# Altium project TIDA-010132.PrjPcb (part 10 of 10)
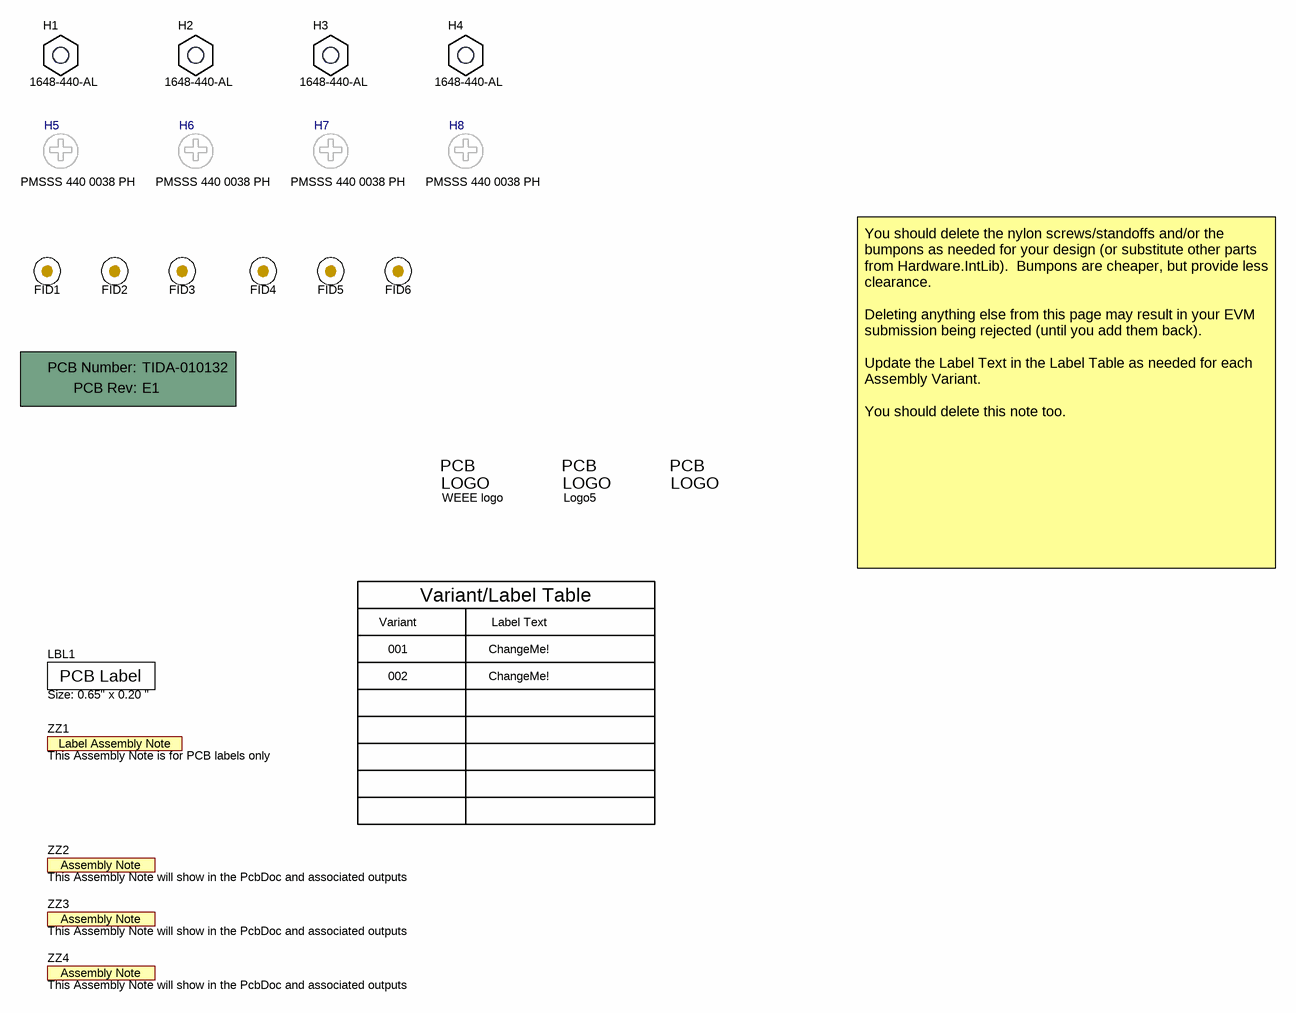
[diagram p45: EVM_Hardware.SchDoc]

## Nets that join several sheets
1P8V_USB: FMC INTERFACE SHEET (9 pins), USB INTERFACE SHEET (34 pins)
3.3V_USB: FMC INTERFACE SHEET (8 pins), CLOCK BUFFER (C419.2 R541.2 U79.16), USB INTERFACE SHEET (40 pins)
+2.5VCLK: CLOCK MAIN SHEET (12 pins), POWER MAIN SHEET1 (6 pins)
+3.3LMK_1: POWER MAIN SHEET1 (5 pins), POWER MAIN SHEET2 (5 pins)
+3.3VCLK: AFE1-LMX2594 (21 pins), CLOCK MAIN SHEET (10 pins), CLOCK MAIN POWER (8 pins), CLOCK BUFFER (14 pins), POWER MAIN SHEET1 (11 pins), POWER MAIN SHEET2 (5 pins), AFE2-LMX2594 (21 pins)
+5V_1: POWER MAIN SHEET1 (J78.1 J78.2 U86.1), POWER MAIN SHEET2 (J55.1 J55.2 U85.1)
+5VIN: FMC INTERFACE SHEET (D7.1 D8.1 D10.1), AFE1-GPIOs (D12.1 D13.1 D14.1), POWER MAIN SHEET1 (6 pins), POWER MAIN SHEET2 (6 pins), USB INTERFACE SHEET (C581.1 R389.1 U33.1), AFE2-GPIOs (D15.1 D16.1 D17.1)
ANALOG_1.0V_1: POWER MAIN SHEET1 (14 pins), POWER MAIN SHEET2 (14 pins)
ANALOG_1.2V_1: POWER MAIN SHEET1 (7 pins), POWER MAIN SHEET2 (7 pins)
ANALOG_1.5V_1: POWER MAIN SHEET1 (7 pins), POWER MAIN SHEET2 (7 pins)
ANALOG_1.8V_1: POWER MAIN SHEET1 (12 pins), POWER MAIN SHEET2 (12 pins)
ANALOG_-1.8V_1: POWER MAIN SHEET1 (7 pins), POWER MAIN SHEET2 (7 pins)
DVDD: AFE1-POWER (41 pins), POWER MAIN SHEET1 (6 pins)
DVDD_1.0V_1: POWER MAIN SHEET1 (13 pins), POWER MAIN SHEET2 (13 pins)
DVDD_2: POWER MAIN SHEET2 (6 pins), AFE2-POWER (41 pins)
GND: 01-MAIN-Sheet (23 pins), FMC INTERFACE SHEET (234 pins), AFE1-RX-INPUTS (96 pins), AFE1-TX-OUTPUTS (45 pins), AFE1-LMX2594 (59 pins), AFE1-POWER (87 pins), AFE1-RX-TX-INTERFACE (26 pins), AFE1-GROUND (136 pins), AFE1-PROGRAMMING INTERFACE (8 pins), AFE1-GPIOs (34 pins), CLOCK MAIN SHEET (72 pins), CLOCK MAIN POWER (26 pins), CLOCK BUFFER (28 pins), POWER MAIN SHEET1 (151 pins), POWER MAIN SHEET2 (140 pins), USB INTERFACE SHEET (94 pins), AFE2-PROGRAMMING INTERFACE (8 pins), AFE2-GPIOs (34 pins), AFE2-RX-INPUTS (96 pins), AFE2-TX-OUTPUTS (45 pins), AFE2-LMX2594 (59 pins), AFE2-POWER (87 pins), AFE2-RX-TX-INTERFACE (26 pins), AFE2-GROUND (136 pins)
RX_1.2V: AFE1-POWER (28 pins), POWER MAIN SHEET1 (5 pins)
RX_1.2V_2: POWER MAIN SHEET2 (5 pins), AFE2-POWER (28 pins)
RX_1.8V: AFE1-POWER (30 pins), POWER MAIN SHEET1 (5 pins)
RX_1.8V_2: POWER MAIN SHEET2 (5 pins), AFE2-POWER (30 pins)
VDDA_1.0V: AFE1-POWER (5 pins), POWER MAIN SHEET1 (5 pins)
VDDA_1.0V_2: POWER MAIN SHEET2 (5 pins), AFE2-POWER (5 pins)
VDDA_1.8V: AFE1-TX-OUTPUTS (16 pins), AFE1-POWER (7 pins), POWER MAIN SHEET1 (5 pins)
VDDA_1.8V_2: POWER MAIN SHEET2 (5 pins), AFE2-TX-OUTPUTS (16 pins), AFE2-POWER (7 pins)
VDDA_SERDES_1.0V: AFE1-POWER (7 pins), POWER MAIN SHEET1 (5 pins)
VDDA_SERDES_1.0V_2: POWER MAIN SHEET2 (5 pins), AFE2-POWER (7 pins)
VDDCLK_1.0V: AFE1-POWER (9 pins), POWER MAIN SHEET1 (5 pins)
VDDCLK_1.0V_2: POWER MAIN SHEET2 (5 pins), AFE2-POWER (9 pins)
VDDE: AFE1-POWER (15 pins), POWER MAIN SHEET1 (5 pins)
VDDE_2: POWER MAIN SHEET2 (5 pins), AFE2-POWER (15 pins)
VDDGPIO_1.8V: AFE1-POWER (C97.1 U3.D17), AFE1-GPIOs (20 pins), POWER MAIN SHEET1 (5 pins)
VDDGPIO_1.8V_2: POWER MAIN SHEET2 (5 pins), AFE2-GPIOs (20 pins), AFE2-POWER (C323.1 U6.D17)
VDDL1_1.0V: AFE1-POWER (9 pins), POWER MAIN SHEET1 (5 pins)
VDDL1_1.0V_2: POWER MAIN SHEET2 (5 pins), AFE2-POWER (9 pins)
VDDL2_1.0V: AFE1-POWER (9 pins), POWER MAIN SHEET1 (5 pins)
VDDL2_1.0V_2: POWER MAIN SHEET2 (5 pins), AFE2-POWER (9 pins)
VDDPLL_1.0V: AFE1-POWER (C73.1 C74.1 U3.K18), POWER MAIN SHEET1 (5 pins)
VDDPLL_1.0V_2: POWER MAIN SHEET2 (5 pins), AFE2-POWER (C299.1 C300.1 U6.K18)
VDDPLL_1.8V: AFE1-POWER (C75.1 C76.1 U3.L18), POWER MAIN SHEET1 (5 pins)
VDDPLL_1.8V_2: POWER MAIN SHEET2 (5 pins), AFE2-POWER (C301.1 C302.1 U6.L18)
VDDR_SERDES_1.5V: AFE1-POWER (7 pins), POWER MAIN SHEET1 (5 pins)
VDDR_SERDES_1.5V_2: POWER MAIN SHEET2 (5 pins), AFE2-POWER (7 pins)
VDDT_SERDES_1.0V: AFE1-POWER (7 pins), POWER MAIN SHEET1 (5 pins)
VDDT_SERDES_1.0V_2: POWER MAIN SHEET2 (5 pins), AFE2-POWER (7 pins)
VDDTX_1.0V: AFE1-POWER (C90.1 C91.1 U3.J15), POWER MAIN SHEET1 (5 pins)
VDDTX_1.0V_2: POWER MAIN SHEET2 (5 pins), AFE2-POWER (C316.1 C317.1 U6.J15)
VDDTX_1.8V: AFE1-POWER (C79.1 C80.1 U3.K16), POWER MAIN SHEET1 (5 pins)
VDDTX_1.8V_2: POWER MAIN SHEET2 (5 pins), AFE2-POWER (C305.1 C306.1 U6.K16)
VDDVCO_1.8V: AFE1-POWER (C77.1 C78.1 U3.L17 U3.M17), POWER MAIN SHEET1 (5 pins)
VDDVCO_1.8V_2: POWER MAIN SHEET2 (5 pins), AFE2-POWER (C303.1 C304.1 U6.L17 U6.M17)
VEE: AFE1-POWER (13 pins), POWER MAIN SHEET1 (5 pins)
VEE_2: POWER MAIN SHEET2 (5 pins), AFE2-POWER (13 pins)
ADC_ALT_SYNC_N: AFE1-PROGRAMMING INTERFACE (U3.N10), AFE2-PROGRAMMING INTERFACE (U6.N10)
ADC_ALT_SYNC_P: AFE1-PROGRAMMING INTERFACE (U3.N11), AFE2-PROGRAMMING INTERFACE (U6.N11)
ADC_SYNC_N: AFE1-PROGRAMMING INTERFACE (U3.H10), AFE2-PROGRAMMING INTERFACE (U6.H10)
ADC_SYNC_P: AFE1-PROGRAMMING INTERFACE (U3.H11), AFE2-PROGRAMMING INTERFACE (U6.H11)
AFE1_AIN1M: AFE1-RX-INPUTS (C117.1), AFE1-RX-TX-INTERFACE (U3.A16)
AFE1_AIN1P: AFE1-RX-INPUTS (C119.1), AFE1-RX-TX-INTERFACE (U3.A17)
AFE1_AIN2M: AFE1-RX-INPUTS (C133.1), AFE1-RX-TX-INTERFACE (U3.A13)
AFE1_AIN2P: AFE1-RX-INPUTS (C135.1), AFE1-RX-TX-INTERFACE (U3.A14)
AFE1_BIN1M: AFE1-RX-INPUTS (C121.1), AFE1-RX-TX-INTERFACE (U3.A10)
AFE1_BIN1P: AFE1-RX-INPUTS (C123.1), AFE1-RX-TX-INTERFACE (U3.A11)
AFE1_BIN2M: AFE1-RX-INPUTS (C137.1), AFE1-RX-TX-INTERFACE (U3.A7)
AFE1_BIN2P: AFE1-RX-INPUTS (C139.1), AFE1-RX-TX-INTERFACE (U3.A8)
AFE1_CIN1M: AFE1-RX-INPUTS (C127.1), AFE1-RX-TX-INTERFACE (U3.Y16)
AFE1_CIN1P: AFE1-RX-INPUTS (C125.1), AFE1-RX-TX-INTERFACE (U3.Y17)
AFE1_CIN2M: AFE1-RX-INPUTS (C143.1), AFE1-RX-TX-INTERFACE (U3.Y13)
AFE1_CIN2P: AFE1-RX-INPUTS (C141.1), AFE1-RX-TX-INTERFACE (U3.Y14)
AFE1_CLKN: AFE1-LMX2594 (R4.1 U1.22), AFE1-RX-TX-INTERFACE (L36.2)
AFE1_CLKP: AFE1-LMX2594 (R1.1 U1.23), AFE1-RX-TX-INTERFACE (L35.2)
AFE1_DCO: AFE1-TX-OUTPUTS (U81.1), AFE2-RX-INPUTS (R546.2)
AFE1_DIN1M: AFE1-RX-INPUTS (C131.1), AFE1-RX-TX-INTERFACE (U3.Y10)
AFE1_DIN1P: AFE1-RX-INPUTS (C129.1), AFE1-RX-TX-INTERFACE (U3.Y11)
AFE1_DIN2M: AFE1-RX-INPUTS (C147.1), AFE1-RX-TX-INTERFACE (U3.Y7)
AFE1_DIN2P: AFE1-RX-INPUTS (C145.1), AFE1-RX-TX-INTERFACE (U3.Y8)
AFE1_DIV_IN: AFE1-RX-TX-INTERFACE (C152.1), CLOCK MAIN SHEET (R344.2)
AFE1_SYSREFN: AFE1-LMX2594 (R563.2 R566.1), AFE1-RX-TX-INTERFACE (R142.2)
AFE1_SYSREFP: AFE1-LMX2594 (R559.1 R562.2), AFE1-RX-TX-INTERFACE (R141.2)
AFE1_TXAM: AFE1-TX-OUTPUTS (L37.1 R147.2 T9.4), AFE1-RX-TX-INTERFACE (U3.C20)
AFE1_TXAP: AFE1-TX-OUTPUTS (L38.2 R147.1 T9.3), AFE1-RX-TX-INTERFACE (U3.B20)
AFE1_TXCM: AFE1-TX-OUTPUTS (L48.2 R159.1 T12.3), AFE1-RX-TX-INTERFACE (U3.V20)
AFE1_TXCP: AFE1-TX-OUTPUTS (L47.1 R159.2 T12.4), AFE1-RX-TX-INTERFACE (U3.W20)
AFE1_TXDM: AFE1-TX-OUTPUTS (L43.1 R155.2 T11.4), AFE1-RX-TX-INTERFACE (U3.R20)
AFE1_TXDP: AFE1-TX-OUTPUTS (L44.2 R155.1 T11.3), AFE1-RX-TX-INTERFACE (U3.P20)
AFE2_AIN1M: AFE2-RX-INPUTS (C343.1), AFE2-RX-TX-INTERFACE (U6.A16)
AFE2_AIN1P: AFE2-RX-INPUTS (C345.1), AFE2-RX-TX-INTERFACE (U6.A17)
AFE2_AIN2M: AFE2-RX-INPUTS (C359.1), AFE2-RX-TX-INTERFACE (U6.A13)
AFE2_AIN2P: AFE2-RX-INPUTS (C361.1), AFE2-RX-TX-INTERFACE (U6.A14)
AFE2_BIN1M: AFE2-RX-INPUTS (C347.1), AFE2-RX-TX-INTERFACE (U6.A10)
AFE2_BIN1P: AFE2-RX-INPUTS (C349.1), AFE2-RX-TX-INTERFACE (U6.A11)
AFE2_BIN2M: AFE2-RX-INPUTS (C363.1), AFE2-RX-TX-INTERFACE (U6.A7)
AFE2_BIN2P: AFE2-RX-INPUTS (C365.1), AFE2-RX-TX-INTERFACE (U6.A8)
AFE2_CIN1M: AFE2-RX-INPUTS (C353.1), AFE2-RX-TX-INTERFACE (U6.Y16)
AFE2_CIN1P: AFE2-RX-INPUTS (C351.1), AFE2-RX-TX-INTERFACE (U6.Y17)
AFE2_CIN2M: AFE2-RX-INPUTS (C369.1), AFE2-RX-TX-INTERFACE (U6.Y13)
AFE2_CIN2P: AFE2-RX-INPUTS (C367.1), AFE2-RX-TX-INTERFACE (U6.Y14)
AFE2_CLKN: AFE2-LMX2594 (R163.1 U4.22), AFE2-RX-TX-INTERFACE (L84.2)
AFE2_CLKP: AFE2-LMX2594 (R160.1 U4.23), AFE2-RX-TX-INTERFACE (L83.2)
AFE2_DCO: AFE1-RX-INPUTS (R544.2), AFE2-TX-OUTPUTS (U82.1)
AFE2_DIN1M: AFE2-RX-INPUTS (C357.1), AFE2-RX-TX-INTERFACE (U6.Y10)
AFE2_DIN1P: AFE2-RX-INPUTS (C355.1), AFE2-RX-TX-INTERFACE (U6.Y11)
AFE2_DIN2M: AFE2-RX-INPUTS (C373.1), AFE2-RX-TX-INTERFACE (U6.Y7)
AFE2_DIN2P: AFE2-RX-INPUTS (C371.1), AFE2-RX-TX-INTERFACE (U6.Y8)
AFE2_DIV_IN: CLOCK MAIN SHEET (R346.2), AFE2-RX-TX-INTERFACE (C378.1)
AFE2_SYSREFN: AFE2-LMX2594 (R575.2 R581.1), AFE2-RX-TX-INTERFACE (R301.2)
AFE2_SYSREFP: AFE2-LMX2594 (R571.1 R574.2), AFE2-RX-TX-INTERFACE (R300.2)
AFE2_TXAM: AFE2-TX-OUTPUTS (L85.1 R306.2 T24.4), AFE2-RX-TX-INTERFACE (U6.C20)
AFE2_TXAP: AFE2-TX-OUTPUTS (L86.2 R306.1 T24.3), AFE2-RX-TX-INTERFACE (U6.B20)
AFE2_TXCM: AFE2-TX-OUTPUTS (L96.2 R318.1 T27.3), AFE2-RX-TX-INTERFACE (U6.V20)
AFE2_TXCP: AFE2-TX-OUTPUTS (L95.1 R318.2 T27.4), AFE2-RX-TX-INTERFACE (U6.W20)
AFE2_TXDM: AFE2-TX-OUTPUTS (L91.1 R314.2 T26.4), AFE2-RX-TX-INTERFACE (U6.R20)
AFE2_TXDP: AFE2-TX-OUTPUTS (L92.2 R314.1 T26.3), AFE2-RX-TX-INTERFACE (U6.P20)
CAR_SYSREFM: FMC INTERFACE SHEET (J53.G10), CLOCK MAIN SHEET (R334.2)
CAR_SYSREFP: FMC INTERFACE SHEET (J53.G9), CLOCK MAIN SHEET (R333.2)
CLK0_M2C_N: FMC INTERFACE SHEET (J53.H5), CLOCK MAIN SHEET (C476.2)
CLK0_M2C_P: FMC INTERFACE SHEET (J53.H4), CLOCK MAIN SHEET (C472.2)
CLK1_M2C_N: FMC INTERFACE SHEET (J53.G3), CLOCK MAIN SHEET (C477.2)
CLK1_M2C_P: FMC INTERFACE SHEET (J53.G2), CLOCK MAIN SHEET (C473.2)
CLK_LAO_0M: FMC INTERFACE SHEET (J53.G7), CLOCK MAIN SHEET (R372.2)
CLK_LAO_0P: FMC INTERFACE SHEET (J53.G6), CLOCK MAIN SHEET (R371.2)
DAC_ALT_SYNC_N: AFE1-PROGRAMMING INTERFACE (U3.P10), AFE2-PROGRAMMING INTERFACE (U6.P10)
DAC_ALT_SYNC_P: AFE1-PROGRAMMING INTERFACE (U3.P11), AFE2-PROGRAMMING INTERFACE (U6.P11)
DAC_SYNC_N: AFE1-PROGRAMMING INTERFACE (U3.G10), AFE2-PROGRAMMING INTERFACE (U6.G10)
DAC_SYNC_P: AFE1-PROGRAMMING INTERFACE (U3.G11), AFE2-PROGRAMMING INTERFACE (U6.G11)
DACOUT: AFE1-GPIOs (R422.2), POWER MAIN SHEET1 (J78.66), POWER MAIN SHEET2 (J55.66), AFE2-GPIOs (R451.2)
DP0_C2M_N: AFE1-SERDES (C183.1), AFE2-SERDES (C409.1)
DP0_C2M_P: AFE1-SERDES (C181.1), AFE2-SERDES (C407.1)
DP0_M2C_N: AFE1-SERDES (C180.2), AFE2-SERDES (C406.2)
DP0_M2C_P: AFE1-SERDES (C178.2), AFE2-SERDES (C404.2)
DP1_C2M_N: AFE1-SERDES (C179.1), AFE2-SERDES (C405.1)
DP1_C2M_P: AFE1-SERDES (C177.1), AFE2-SERDES (C403.1)
DP1_M2C_N: AFE1-SERDES (C184.2), AFE2-SERDES (C410.2)
DP1_M2C_P: AFE1-SERDES (C182.2), AFE2-SERDES (C408.2)
DP2_C2M_N: AFE1-SERDES (C175.1), AFE2-SERDES (C401.1)
DP2_C2M_P: AFE1-SERDES (C173.1), AFE2-SERDES (C399.1)
DP2_M2C_N: AFE1-SERDES (C176.2), AFE2-SERDES (C402.2)
DP2_M2C_P: AFE1-SERDES (C174.2), AFE2-SERDES (C400.2)
DP3_C2M_N: AFE1-SERDES (C171.1), AFE2-SERDES (C397.1)
DP3_C2M_P: AFE1-SERDES (C169.1), AFE2-SERDES (C395.1)
DP3_M2C_N: AFE1-SERDES (C172.2), AFE2-SERDES (C398.2)
DP3_M2C_P: AFE1-SERDES (C170.2), AFE2-SERDES (C396.2)
DP4_C2M_N: AFE1-SERDES (C161.1), AFE2-SERDES (C387.1)
DP4_C2M_P: AFE1-SERDES (C163.1), AFE2-SERDES (C389.1)
DP4_M2C_N: AFE1-SERDES (C162.2), AFE2-SERDES (C388.2)
DP4_M2C_P: AFE1-SERDES (C164.2), AFE2-SERDES (C390.2)
DP5_C2M_N: AFE1-SERDES (C153.1), AFE2-SERDES (C379.1)
DP5_C2M_P: AFE1-SERDES (C155.1), AFE2-SERDES (C381.1)
DP5_M2C_N: AFE1-SERDES (C154.2), AFE2-SERDES (C380.2)
DP5_M2C_P: AFE1-SERDES (C156.2), AFE2-SERDES (C382.2)
DP6_C2M_N: AFE1-SERDES (C157.1), AFE2-SERDES (C383.1)
DP6_C2M_P: AFE1-SERDES (C159.1), AFE2-SERDES (C385.1)
DP6_M2C_N: AFE1-SERDES (C158.2), AFE2-SERDES (C384.2)
DP6_M2C_P: AFE1-SERDES (C160.2), AFE2-SERDES (C386.2)
DP7_C2M_N: AFE1-SERDES (C165.1), AFE2-SERDES (C391.1)
DP7_C2M_P: AFE1-SERDES (C167.1), AFE2-SERDES (C393.1)
DP7_M2C_N: AFE1-SERDES (C166.2), AFE2-SERDES (C392.2)
DP7_M2C_P: AFE1-SERDES (C168.2), AFE2-SERDES (C394.2)
FMC_FBBANDSEL1: AFE1-GPIOs (R206.16), AFE2-GPIOs (R465.16)
FMC_FBBANDSEL2: AFE1-GPIOs (R206.15), AFE2-GPIOs (R465.15)
FMC_FSPICLKA: AFE1-PROGRAMMING INTERFACE (R43.16), AFE2-PROGRAMMING INTERFACE (R49.16)
FMC_FSPICLKB: AFE1-PROGRAMMING INTERFACE (R43.14), AFE2-PROGRAMMING INTERFACE (R49.14)
FMC_FSPICLKC: AFE1-PROGRAMMING INTERFACE (R43.12), AFE2-PROGRAMMING INTERFACE (R49.12)
FMC_FSPICLKD: AFE1-PROGRAMMING INTERFACE (R43.10), AFE2-PROGRAMMING INTERFACE (R49.10)
FMC_FSPIDA: AFE1-PROGRAMMING INTERFACE (R43.15), AFE2-PROGRAMMING INTERFACE (R49.15)
FMC_FSPIDB: AFE1-PROGRAMMING INTERFACE (R43.13), AFE2-PROGRAMMING INTERFACE (R49.13)
FMC_FSPIDC: AFE1-PROGRAMMING INTERFACE (R43.11), AFE2-PROGRAMMING INTERFACE (R49.11)
FMC_FSPIDD: AFE1-PROGRAMMING INTERFACE (R43.9), AFE2-PROGRAMMING INTERFACE (R49.9)
FMC_LMK_CS: FMC INTERFACE SHEET (J53.H17 U40.12), USB INTERFACE SHEET (U74.9)
FMC_LMK_SCK: FMC INTERFACE SHEET (J53.G15 U40.15), USB INTERFACE SHEET (U74.6)
FMC_LMK_SDIO: FMC INTERFACE SHEET (J53.G16 U40.14), USB INTERFACE SHEET (U74.7)
FMC_LMK_SDO: FMC INTERFACE SHEET (J53.H16 U40.13), USB INTERFACE SHEET (U74.8)
FMC_LMX_CS: FMC INTERFACE SHEET (U40.16), USB INTERFACE SHEET (U74.5)
FMC_LMX_SCK: FMC INTERFACE SHEET (U40.20), USB INTERFACE SHEET (U74.1)
FMC_LMX_SDIO: FMC INTERFACE SHEET (U40.18), USB INTERFACE SHEET (U74.3)
FMC_LMX_SDO: FMC INTERFACE SHEET (U40.17), USB INTERFACE SHEET (U74.4)
FMC_RXADSA1PD: AFE1-GPIOs (R53.14), AFE2-GPIOs (R208.14)
FMC_RXADSA2PD: AFE1-GPIOs (R53.13), AFE2-GPIOs (R208.13)
FMC_RXADSAFAST: AFE1-GPIOs (R202.16), AFE2-GPIOs (R461.16)
FMC_RXAPD2H: AFE1-GPIOs (R198.14), AFE2-GPIOs (R210.14)
FMC_RXAPD2L: AFE1-GPIOs (R198.13), AFE2-GPIOs (R210.13)
FMC_RXBDSA1PD: AFE1-GPIOs (R53.12), AFE2-GPIOs (R208.12)
FMC_RXBDSA2PD: AFE1-GPIOs (R53.11), AFE2-GPIOs (R208.11)
FMC_RXBDSAFAST: AFE1-GPIOs (R202.15), AFE2-GPIOs (R461.15)
FMC_RXBPD2H: AFE1-GPIOs (R198.12), AFE2-GPIOs (R210.12)
FMC_RXBPD2L: AFE1-GPIOs (R198.11), AFE2-GPIOs (R210.11)
FMC_RXCDSA1PD: AFE1-GPIOs (R53.10), AFE2-GPIOs (R208.10)
FMC_RXCDSA2PD: AFE1-GPIOs (R53.9), AFE2-GPIOs (R208.9)
FMC_RXCDSAFAST: AFE1-GPIOs (R202.14), AFE2-GPIOs (R461.14)
FMC_RXDDSA1PD: AFE1-GPIOs (R198.16), AFE2-GPIOs (R210.16)
FMC_RXDDSA2PD: AFE1-GPIOs (R198.15), AFE2-GPIOs (R210.15)
FMC_RXDDSAFAST: AFE1-GPIOs (R202.13), AFE2-GPIOs (R461.13)
FMC_RXDSASW: AFE1-GPIOs (R204.9), AFE2-GPIOs (R463.9)
FMC_RXFBNCO0: AFE1-GPIOs (R202.12), AFE2-GPIOs (R461.12)
FMC_RXFBNCO1: AFE1-GPIOs (R202.11), AFE2-GPIOs (R461.11)
FMC_RXFBNCO2: AFE1-GPIOs (R202.10), AFE2-GPIOs (R461.10)
FMC_RXFBNCO3: AFE1-GPIOs (R202.9), AFE2-GPIOs (R461.9)
FMC_RXFBSW1: AFE1-GPIOs (R204.12), AFE2-GPIOs (R463.12)
FMC_RXFBSW2: AFE1-GPIOs (R204.11), AFE2-GPIOs (R463.11)
FMC_RXTDD1: AFE1-GPIOs (R204.14), AFE2-GPIOs (R463.14)
FMC_RXTDD2: AFE1-GPIOs (R204.13), AFE2-GPIOs (R463.13)
FMC_SPIACLK: AFE1-PROGRAMMING INTERFACE (R40.2), AFE2-PROGRAMMING INTERFACE (R46.2)
FMC_SPIASDIO: AFE1-PROGRAMMING INTERFACE (R40.4), AFE2-PROGRAMMING INTERFACE (R46.4)
FMC_SPIASDO: AFE1-PROGRAMMING INTERFACE (R40.3), AFE2-PROGRAMMING INTERFACE (R46.3)
FMC_SPIASEN: AFE1-PROGRAMMING INTERFACE (R40.1), AFE2-PROGRAMMING INTERFACE (R46.1)
FMC_SPIBCLK: AFE1-PROGRAMMING INTERFACE (R40.6), AFE2-PROGRAMMING INTERFACE (R46.6)
FMC_SPIBSDIO: AFE1-PROGRAMMING INTERFACE (R40.8), AFE2-PROGRAMMING INTERFACE (R46.8)
FMC_SPIBSDO: AFE1-PROGRAMMING INTERFACE (R40.7), AFE2-PROGRAMMING INTERFACE (R46.7)
FMC_SPIBSEN: AFE1-PROGRAMMING INTERFACE (R40.5), AFE2-PROGRAMMING INTERFACE (R46.5)
FMC_TCK: AFE1-PROGRAMMING INTERFACE (R39.16), AFE2-PROGRAMMING INTERFACE (R45.16)
FMC_TDI: AFE1-PROGRAMMING INTERFACE (R39.15), AFE2-PROGRAMMING INTERFACE (R45.15)
FMC_TDO: AFE1-PROGRAMMING INTERFACE (R39.14), AFE2-PROGRAMMING INTERFACE (R45.14)
FMC_TMS: AFE1-PROGRAMMING INTERFACE (R39.13), AFE2-PROGRAMMING INTERFACE (R45.13)
FMC_TRSTB: AFE1-PROGRAMMING INTERFACE (R39.12), AFE2-PROGRAMMING INTERFACE (R45.12)
FMC_TXDSASW: AFE1-GPIOs (R204.10), AFE2-GPIOs (R463.10)
FMC_TXTDD1: AFE1-GPIOs (R204.16), AFE2-GPIOs (R463.16)
FMC_TXTDD2: AFE1-GPIOs (R204.15), AFE2-GPIOs (R463.15)
FPGA_CLK1_N: FMC INTERFACE SHEET (J53.K5), CLOCK MAIN SHEET (C497.2)
FPGA_CLK1_P: FMC INTERFACE SHEET (J53.K4), CLOCK MAIN SHEET (C495.2)
FPGA_CLK2_N: FMC INTERFACE SHEET (J53.J3), CLOCK MAIN SHEET (C501.2)
FPGA_CLK2_P: FMC INTERFACE SHEET (J53.J2), CLOCK MAIN SHEET (C500.2)
FTDI_FSPICLKA: AFE1-PROGRAMMING INTERFACE (R42.1), AFE2-PROGRAMMING INTERFACE (R48.1)
FTDI_FSPICLKB: AFE1-PROGRAMMING INTERFACE (R42.3), AFE2-PROGRAMMING INTERFACE (R48.3)
FTDI_FSPICLKC: AFE1-PROGRAMMING INTERFACE (R42.5), AFE2-PROGRAMMING INTERFACE (R48.5)
FTDI_FSPICLKD: AFE1-PROGRAMMING INTERFACE (R42.7), AFE2-PROGRAMMING INTERFACE (R48.7)
FTDI_FSPIDA: AFE1-PROGRAMMING INTERFACE (R42.2), AFE2-PROGRAMMING INTERFACE (R48.2)
FTDI_FSPIDB: AFE1-PROGRAMMING INTERFACE (R42.4), AFE2-PROGRAMMING INTERFACE (R48.4)
FTDI_FSPIDC: AFE1-PROGRAMMING INTERFACE (R42.6), AFE2-PROGRAMMING INTERFACE (R48.6)
FTDI_FSPIDD: AFE1-PROGRAMMING INTERFACE (R42.8), AFE2-PROGRAMMING INTERFACE (R48.8)
FTDI_SPIACLK: AFE1-PROGRAMMING INTERFACE (R41.15), AFE2-PROGRAMMING INTERFACE (R47.15)
FTDI_SPIASDIO: AFE1-PROGRAMMING INTERFACE (R41.13), AFE2-PROGRAMMING INTERFACE (R47.13)
FTDI_SPIASDO: AFE1-PROGRAMMING INTERFACE (R41.14), AFE2-PROGRAMMING INTERFACE (R47.14)
FTDI_SPIASEN: AFE1-PROGRAMMING INTERFACE (R41.16), AFE2-PROGRAMMING INTERFACE (R47.16)
FTDI_SPIBCLK: AFE1-PROGRAMMING INTERFACE (R41.11), AFE2-PROGRAMMING INTERFACE (R47.11)
FTDI_SPIBSDIO: AFE1-PROGRAMMING INTERFACE (R41.9), AFE2-PROGRAMMING INTERFACE (R47.9)
FTDI_SPIBSDO: AFE1-PROGRAMMING INTERFACE (R41.10), AFE2-PROGRAMMING INTERFACE (R47.10)
FTDI_SPIBSEN: AFE1-PROGRAMMING INTERFACE (R41.12), AFE2-PROGRAMMING INTERFACE (R47.12)
FTDI_TCK: AFE1-PROGRAMMING INTERFACE (R38.1), AFE2-PROGRAMMING INTERFACE (R44.1)
FTDI_TDI: AFE1-PROGRAMMING INTERFACE (R38.2), AFE2-PROGRAMMING INTERFACE (R44.2)
FTDI_TDO: AFE1-PROGRAMMING INTERFACE (R38.3), AFE2-PROGRAMMING INTERFACE (R44.3)
FTDI_TMS: AFE1-PROGRAMMING INTERFACE (R38.4), AFE2-PROGRAMMING INTERFACE (R44.4)
FTDI_TRSTB: AFE1-PROGRAMMING INTERFACE (R38.5), AFE2-PROGRAMMING INTERFACE (R44.5)
GBTCLK1_M2C_N: FMC INTERFACE SHEET (J53.B21), CLOCK MAIN SHEET (C478.2)
GBTCLK1_M2C_P: FMC INTERFACE SHEET (J53.B20), CLOCK MAIN SHEET (C474.2)
GTX_CLKM: FMC INTERFACE SHEET (J53.D5), CLOCK MAIN SHEET (C479.2)
GTX_CLKP: FMC INTERFACE SHEET (J53.D4), CLOCK MAIN SHEET (C475.2)
I2C_SCL: FMC INTERFACE SHEET (U63.6), USB INTERFACE SHEET (J21.1 R488.1)
I2C_SDA: FMC INTERFACE SHEET (U63.7), USB INTERFACE SHEET (J21.2 R491.1)
LMK_AFE1_CLKM: AFE1-LMX2594 (R29.1), AFE1-RX-TX-INTERFACE (R376.1), CLOCK MAIN SHEET (C490.2)
LMK_AFE1_CLKP: AFE1-LMX2594 (R27.1), AFE1-RX-TX-INTERFACE (R375.1), CLOCK MAIN SHEET (C488.2)
LMK_AFE1_SYSREFM: AFE1-LMX2594 (R548.1), AFE1-RX-TX-INTERFACE (R378.2), CLOCK MAIN SHEET (R347.2 R350.2)
LMK_AFE1_SYSREFP: AFE1-LMX2594 (R549.1), AFE1-RX-TX-INTERFACE (R377.2), CLOCK MAIN SHEET (R345.2 R351.2)
LMK_AFE2_CLKM: CLOCK MAIN SHEET (C226.2), AFE2-LMX2594 (R188.1), AFE2-RX-TX-INTERFACE (R482.1)
LMK_AFE2_CLKP: CLOCK MAIN SHEET (C225.2), AFE2-LMX2594 (R186.1), AFE2-RX-TX-INTERFACE (R481.1)
LMK_AFE2_SYSREFM: CLOCK MAIN SHEET (R504.2 R509.2), AFE2-LMX2594 (R550.1), AFE2-RX-TX-INTERFACE (R502.2)
LMK_AFE2_SYSREFP: CLOCK MAIN SHEET (R503.2 R510.2), AFE2-LMX2594 (R551.1), AFE2-RX-TX-INTERFACE (R501.2)
LMK_CS: CLOCK MAIN POWER (C458.2 U7.18), USB INTERFACE SHEET (J22.6 R492.9 R493.8)
LMK_SCK: CLOCK MAIN POWER (C457.2 U7.19), USB INTERFACE SHEET (J22.2 R492.12 R493.5)
LMK_SDIO: CLOCK MAIN POWER (C456.2 U7.20), USB INTERFACE SHEET (J22.4 R492.11 R493.6)
LMK_SDO: CLOCK MAIN POWER (R319.1 U7.5), USB INTERFACE SHEET (J22.8 R492.10 R493.7)
LMX1_REFN: AFE1-LMX2594 (R35.1), CLOCK BUFFER (R521.2 R522.1 R524.2)
LMX1_REFP: AFE1-LMX2594 (R19.2), CLOCK BUFFER (R518.1 R520.2 R525.2)
LMX1_SDO: AFE1-LMX2594 (R20.2), USB INTERFACE SHEET (U75.1)
LMX2_REFN: CLOCK BUFFER (R530.2 R531.1 R534.2), AFE2-LMX2594 (R194.1)
LMX2_REFP: CLOCK BUFFER (R526.1 R528.2 R535.2), AFE2-LMX2594 (R178.2)
LMX2_SDO: USB INTERFACE SHEET (U75.3), AFE2-LMX2594 (R179.2)
LMX_CS: AFE1-LMX2594 (U1.24), AFE2-LMX2594 (U4.24)
LMX_SCK: AFE1-LMX2594 (U1.16), USB INTERFACE SHEET (J22.1 R492.16 R493.1), AFE2-LMX2594 (U4.16)
LMX_SDIO: AFE1-LMX2594 (U1.17), USB INTERFACE SHEET (J22.3 R492.15 R493.2), AFE2-LMX2594 (U4.17)
NB7_RESET: FMC INTERFACE SHEET (R387.1), CLOCK MAIN SHEET (U8.15)
POWER_CLKN: CLOCK BUFFER (U78.18), POWER MAIN SHEET1 (J78.61), POWER MAIN SHEET2 (J55.61)
POWER_CLKP: CLOCK BUFFER (U78.19), POWER MAIN SHEET1 (J78.63), POWER MAIN SHEET2 (J55.63)
SCL: CLOCK MAIN SHEET (R474.1 U69.8), CLOCK BUFFER (U79.14), POWER MAIN SHEET1 (J78.65), POWER MAIN SHEET2 (J55.65), USB INTERFACE SHEET (R51.1 R488.2 R489.1 U65.14)
SDA: CLOCK MAIN SHEET (R475.1 U69.7), CLOCK BUFFER (U79.15), POWER MAIN SHEET1 (J78.67), POWER MAIN SHEET2 (J55.67), USB INTERFACE SHEET (R487.1 R490.1 R491.2 U65.15)
SDCLKout11_N: AFE1-LMX2594 (R26.1 U2.1), CLOCK MAIN SHEET (U7.57)
SDCLKout11_P: AFE1-LMX2594 (R25.2 R26.2 U2.2), CLOCK MAIN SHEET (U7.56)
SDCLKout13_N: CLOCK MAIN SHEET (U7.61), AFE2-LMX2594 (R185.1 U5.1)
SDCLKout13_P: CLOCK MAIN SHEET (U7.60), AFE2-LMX2594 (R184.2 R185.2 U5.2)
SEL_SPI: FMC INTERFACE SHEET (U40.10), USB INTERFACE SHEET (U65.6 U66.10 U74.10)
syncb0cmos: AFE1-PROGRAMMING INTERFACE (U3.E13), AFE2-PROGRAMMING INTERFACE (U6.E13)
syncb1cmos: AFE1-PROGRAMMING INTERFACE (U3.C8), AFE2-PROGRAMMING INTERFACE (U6.C8)
syncb2cmos: AFE1-PROGRAMMING INTERFACE (U3.T13), AFE2-PROGRAMMING INTERFACE (U6.T13)
syncb3cmos: AFE1-PROGRAMMING INTERFACE (U3.V8), AFE2-PROGRAMMING INTERFACE (U6.V8)

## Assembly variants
001: not fitted FID1 FID2 FID3 FID4 FID5 FID6 L3 L5 L6 L7 L9 L10 L11 L13 L14 L15 L17 L18 L19 L21 L22 L23 L25 L26 L27 L29 L30 L31 L33 L34 L51 L53 L54 L55 L57 L58 L59 L61 L62 L63 L65 L66 L67 L69 L70 L71 L73 L74 L75 L77 L78 L79 L81 L82 R23 R25 R27 R29 R30 R32 R39 R40 R43 R45 R46 R49 R53 R58 R59 R67 R68 R76 R77 R85 R86 R94 R95 R103 R104 R112 R113 R121 R122 R126 R127 R128 R131 R134 R136 R137 R139 R143 R145 R146 R149 R150 R153 R154 R157 R158 R182 R184 R186 R188 R189 R191 R198 R200 R202 R204 R206 R208 R210 R212 R217 R218 R226 R227 R235 R236 R244 R245 R253 R254 R262 R263 R271 R272 R280 R281 R285 R286 R287 R290 R293 R295 R296 R298 R302 R304 R305 R308 R309 R312 R313 R316 R317 R375 R376 R377 R378 R461 R463 R465 R468 R471 R481 R482 R493 R501 R502 R518 R519 R522 R523 R526 R527 R531 R532 R542 R543 R544 R546 R552 R559 R566 R571 R581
